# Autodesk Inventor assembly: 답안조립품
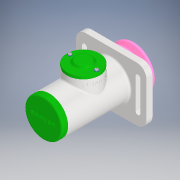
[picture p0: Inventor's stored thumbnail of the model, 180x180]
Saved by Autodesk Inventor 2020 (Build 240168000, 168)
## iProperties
Created: 2021-07
Part Number: 답안조립품
Document SubType Name: Assembly
Designer: MIRAE
Author: MIRAE
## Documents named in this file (20)
- C:\Users\MIRAE\Desktop\710706V1026\답안조립품.iam
- C:\Users\MIRAE\Desktop\710706V1026\본체.ipt
- C:\Users\MIRAE\Desktop\710706V1026\V-벨트풀리.ipt
- C:\Users\MIRAE\Desktop\710706V1026\너트 M10.ipt
- C:\Users\MIRAE\Desktop\710706V1026\멈춤링 15 x 1.ipt
- C:\Users\MIRAE\Desktop\710706V1026\멈춤링 35 x 1.6.ipt
- C:\Users\MIRAE\Desktop\710706V1026\베어링 15 x 35 x 11.ipt
- C:\Users\MIRAE\Desktop\710706V1026\볼트 M4 x 10.ipt
- C:\Users\MIRAE\Desktop\710706V1026\부시1.ipt
- C:\Users\MIRAE\Desktop\710706V1026\부시2.ipt
- C:\Users\MIRAE\Desktop\710706V1026\사이드 커버.ipt
- 사이드 커버.ipt
- C:\Users\MIRAE\Desktop\710706V1026\십자볼트 M3 x 10.ipt
- C:\Users\MIRAE\Desktop\710706V1026\오일 실 15 25 7.ipt
- C:\Users\MIRAE\Desktop\710706V1026\와셔 3 x 6.ipt
- C:\Users\MIRAE\Desktop\710706V1026\와셔 4 x 16.ipt
- C:\Users\MIRAE\Desktop\710706V1026\와셔 10 x 21.ipt
- C:\Users\MIRAE\Desktop\710706V1026\축.ipt
- C:\Users\MIRAE\Desktop\710706V1026\키 4 x 4 x 18.ipt
- C:\Users\MIRAE\Desktop\710706V1026\탑 커버.ipt
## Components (2 placed, 2 different names)
1. V-벨트풀리:1
2. ISO 4017 M4 x 10:1 — 각도:3
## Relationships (1: Angle 1)
- 각도:3 [Angle]: ISO 4017 M4 x 10:1
